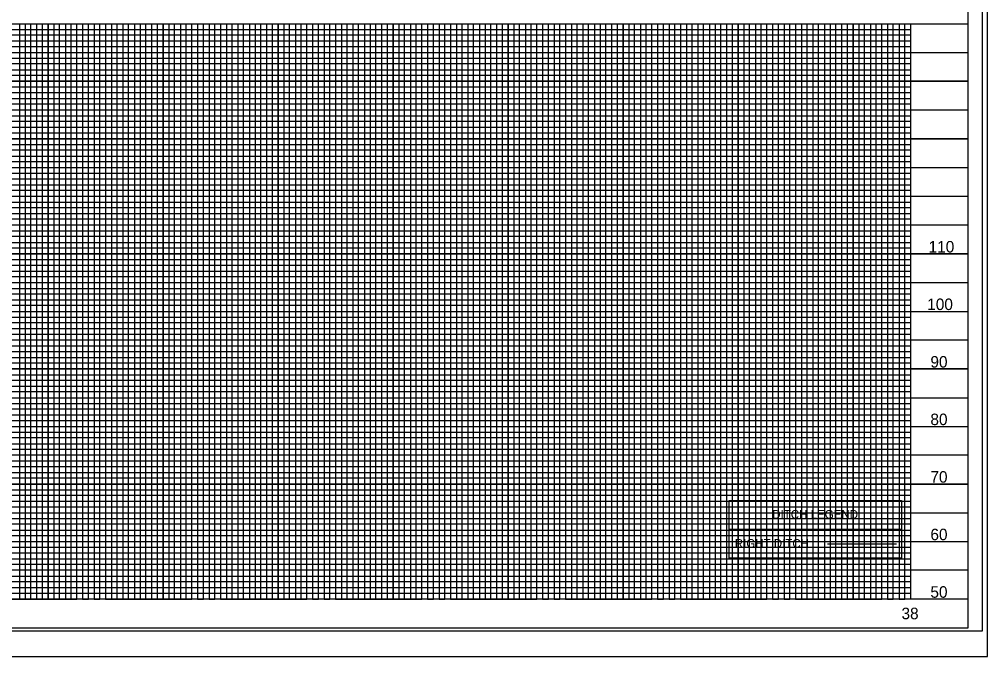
# Model space of a CAD drawing. Extents: x 2367101 to 2368930, y 803279 to 808979.
# Drawn here: x 2367943 to 2368785, y 803279 to 803833 of the extents above; entities that cross this region are included whole.
import ezdxf

# ---------------------------------------------------------------- set-up
doc = ezdxf.new("R2010")
doc.units = 0
for name, color, linetype in [('Old_Level_11', 7, 'Continuous'), ('Old_Level_12', 7, 'Continuous'), ('Old_Level_13', 7, 'Continuous'), ('Old_Level_15', 7, 'Continuous'), ('Old_Level_17', 7, 'Continuous'), ('Old_Level_19', 7, 'Continuous'), ('Old_Level_4', 7, 'Continuous'), ('Old_Level_5', 7, 'Continuous'), ('Old_Level_6', 7, 'Continuous'), ('Old_Level_60', 7, 'Continuous'), ('Old_Level_8', 7, 'Continuous'), ('Old_Level_9', 7, 'Continuous'), ('Text', 7, 'Continuous')]:
    doc.layers.add(name, color=color, linetype=linetype)

msp = doc.modelspace()

# ---------------------------------------------------------------- linework, layer by layer
at = {"layer": 'Old_Level_11'}
for p, q in [((2367967.97, 803828.98), (2368017.97, 803828.98)), ((2368067.97, 803828.98), (2368117.97, 803828.98)), ((2368167.97, 803828.98), (2368217.97, 803828.98)), ((2368267.97, 803828.98), (2368317.97, 803828.98)), ((2368367.97, 803828.98), (2368417.97, 803828.98)), ((2368467.97, 803828.98), (2368517.97, 803828.98)), ((2368567.97, 803828.98), (2368617.97, 803828.98)), ((2368667.97, 803828.98), (2368717.97, 803828.98)), ((2368667.97, 803328.98), (2368667.97, 803328.98))]:
    msp.add_line(p, q, dxfattribs=at)
for points in [[(2367917.97, 803328.98), (2367967.97, 803328.98), (2367967.97, 803828.98), (2368017.97, 803828.98), (2368017.97, 803328.98), (2368067.97, 803328.98), (2368067.97, 803828.98), (2368117.97, 803828.98), (2368117.97, 803328.98), (2368167.97, 803328.98), (2368167.97, 803828.98), (2368217.97, 803828.98), (2368217.97, 803328.98), (2368267.97, 803328.98), (2368267.97, 803828.98), (2368317.97, 803828.98), (2368317.97, 803328.98), (2368367.97, 803328.98), (2368367.97, 803828.98), (2368417.97, 803828.98), (2368417.97, 803328.98), (2368467.97, 803328.98), (2368467.97, 803828.98), (2368517.97, 803828.98), (2368517.97, 803328.98), (2368567.97, 803328.98), (2368567.97, 803828.98), (2368617.97, 803828.98), (2368617.97, 803328.98), (2368667.97, 803328.98), (2368667.97, 803328.98), (2368667.97, 803828.98), (2368717.97, 803828.98), (2368717.97, 803328.98)], [(2368767.97, 803778.98), (2367267.97, 803778.98)], [(2368767.97, 803728.98), (2367267.97, 803728.98), (2367267.97, 803678.98), (2368767.97, 803678.98)], [(2368767.97, 803628.98), (2367267.97, 803628.98), (2367267.97, 803578.98), (2368767.97, 803578.98)], [(2368767.97, 803528.98), (2367267.97, 803528.98), (2367267.97, 803478.98), (2368767.97, 803478.98)], [(2368767.97, 803428.98), (2367267.97, 803428.98), (2367267.97, 803428.98), (2367267.97, 803378.98), (2368767.97, 803378.98)], [(2368767.97, 803328.98), (2367267.97, 803328.98)]]:
    msp.add_lwpolyline(points, dxfattribs=at)
at = {"layer": 'Old_Level_12'}
for points in [[(2367892.97, 803828.98), (2367942.97, 803828.98), (2367942.97, 803328.98), (2367992.97, 803328.98), (2367992.97, 803828.98), (2368042.97, 803828.98), (2368042.97, 803328.98), (2368092.97, 803328.98), (2368092.97, 803828.98), (2368142.97, 803828.98), (2368142.97, 803328.98), (2368192.97, 803328.98), (2368192.97, 803828.98), (2368242.97, 803828.98), (2368242.97, 803328.98), (2368292.97, 803328.98), (2368292.97, 803828.98), (2368342.97, 803828.98), (2368342.97, 803328.98), (2368392.97, 803328.98), (2368392.97, 803828.98), (2368442.97, 803828.98), (2368442.97, 803328.98), (2368492.97, 803328.98), (2368492.97, 803828.98), (2368542.97, 803828.98), (2368542.97, 803328.98), (2368592.97, 803328.98), (2368592.97, 803828.98), (2368642.97, 803828.98), (2368642.97, 803328.98), (2368692.97, 803328.98), (2368692.97, 803828.98)], [(2367267.97, 803803.98), (2368767.97, 803803.98)], [(2368767.97, 803753.98), (2367267.97, 803753.98), (2367267.97, 803703.98), (2368767.97, 803703.98)], [(2368767.97, 803653.98), (2367267.97, 803653.98), (2367267.97, 803603.98), (2368767.97, 803603.98)], [(2368767.97, 803553.98), (2367267.97, 803553.98), (2367267.97, 803503.98), (2368767.97, 803503.98)], [(2368767.97, 803453.98), (2367267.97, 803453.98), (2367267.97, 803403.98), (2368767.97, 803403.98)], [(2368767.97, 803353.98), (2367267.97, 803353.98)]]:
    msp.add_lwpolyline(points, dxfattribs=at)
at = {"layer": 'Old_Level_13'}
for p, q in [((2367267.97, 803828.98), (2368767.86, 803828.98)), ((2367967.97, 803828.98), (2367967.97, 803328.98)), ((2368017.97, 803828.98), (2368017.97, 803328.98)), ((2368067.97, 803828.98), (2368067.97, 803328.98)), ((2368117.97, 803828.98), (2368117.97, 803328.98)), ((2368167.97, 803828.98), (2368167.97, 803328.98)), ((2368217.97, 803828.98), (2368217.97, 803328.98)), ((2368267.97, 803828.98), (2368267.97, 803328.98)), ((2368317.97, 803828.98), (2368317.97, 803328.98)), ((2368367.97, 803828.98), (2368367.97, 803328.98)), ((2368417.97, 803828.98), (2368417.97, 803328.98)), ((2368467.97, 803828.98), (2368467.97, 803328.98)), ((2368517.97, 803828.98), (2368517.97, 803328.98)), ((2368567.97, 803828.98), (2368567.97, 803328.98)), ((2368617.97, 803828.98), (2368617.97, 803328.98)), ((2368667.97, 803828.98), (2368667.97, 803328.98)), ((2368717.97, 803828.98), (2368717.97, 803328.98)), ((2367267.97, 803778.98), (2368767.86, 803778.98)), ((2367267.97, 803728.98), (2368767.86, 803728.98)), ((2367267.97, 803678.98), (2368767.86, 803678.98)), ((2367267.97, 803628.98), (2368767.86, 803628.98)), ((2367267.97, 803578.98), (2368767.86, 803578.98)), ((2367267.97, 803528.98), (2368767.86, 803528.98)), ((2367267.97, 803478.98), (2368767.86, 803478.98)), ((2367267.97, 803428.98), (2368767.86, 803428.98)), ((2367267.97, 803378.98), (2368767.86, 803378.98))]:
    msp.add_line(p, q, dxfattribs=at)
at = {"layer": 'Old_Level_15'}
msp.add_line((2367100.97, 803278.98), (2368784.97, 803278.98), dxfattribs=at)
at = {"layer": 'Old_Level_4'}
msp.add_lwpolyline([(2367113.97, 803301.43), (2368780.47, 803301.43), (2368780.47, 804356.53), (2367113.97, 804356.53)], close=True, dxfattribs=at)
at = {"layer": 'Old_Level_5'}
msp.add_lwpolyline([(2367317.97, 803828.98), (2368717.97, 803828.98), (2368717.97, 803328.98), (2367317.97, 803328.98)], close=True, dxfattribs=at)
at = {"layer": 'Old_Level_6'}
msp.add_lwpolyline([(2367100.97, 803278.98), (2368784.97, 803278.98), (2368784.97, 804378.98), (2367100.97, 804378.98)], close=True, dxfattribs=at)
at = {"layer": 'Old_Level_60'}
for points in [[(2368560.13, 803414.54), (2368710.13, 803414.54), (2368710.13, 803389.54), (2368560.13, 803389.54)], [(2368560.13, 803389.54), (2368710.13, 803389.54), (2368710.13, 803364.54), (2368560.13, 803364.54)]]:
    msp.add_lwpolyline(points, close=True, dxfattribs=at)
at = {"layer": 'Old_Level_8'}
for p, q in [((2367317.97, 803823.98), (2368717.97, 803823.98)), ((2368717.97, 803818.98), (2367317.97, 803818.98)), ((2367317.97, 803813.98), (2368717.97, 803813.98)), ((2368717.97, 803808.98), (2367317.97, 803808.98)), ((2367317.97, 803798.98), (2368717.97, 803798.98)), ((2368717.97, 803793.98), (2367317.97, 803793.98)), ((2367317.97, 803788.98), (2368717.97, 803788.98)), ((2368717.97, 803783.98), (2367317.97, 803783.98)), ((2367317.97, 803773.98), (2368717.97, 803773.98)), ((2368717.97, 803768.98), (2367317.97, 803768.98)), ((2367317.97, 803763.98), (2368717.97, 803763.98)), ((2368717.97, 803758.98), (2367317.97, 803758.98)), ((2367317.97, 803748.98), (2368717.97, 803748.98)), ((2368717.97, 803743.98), (2367317.97, 803743.98)), ((2367317.97, 803738.98), (2368717.97, 803738.98)), ((2368717.97, 803733.98), (2367317.97, 803733.98)), ((2367317.97, 803723.98), (2368717.97, 803723.98)), ((2368717.97, 803718.98), (2367317.97, 803718.98)), ((2367317.97, 803713.98), (2368717.97, 803713.98)), ((2368717.97, 803708.98), (2367317.97, 803708.98)), ((2367317.97, 803698.98), (2368717.97, 803698.98)), ((2368717.97, 803693.98), (2367317.97, 803693.98)), ((2367317.97, 803688.98), (2368717.97, 803688.98)), ((2368717.97, 803683.98), (2367317.97, 803683.98)), ((2367317.97, 803673.98), (2368717.97, 803673.98)), ((2368717.97, 803668.98), (2367317.97, 803668.98)), ((2367317.97, 803663.98), (2368717.97, 803663.98)), ((2368717.97, 803658.98), (2367317.97, 803658.98)), ((2367317.97, 803648.98), (2368717.97, 803648.98)), ((2368717.97, 803643.98), (2367317.97, 803643.98)), ((2367317.97, 803638.98), (2368717.97, 803638.98)), ((2368717.97, 803633.98), (2367317.97, 803634.13)), ((2367317.97, 803623.98), (2368717.97, 803623.98)), ((2368717.97, 803618.98), (2367317.97, 803618.98)), ((2367317.97, 803613.98), (2368717.97, 803613.98)), ((2368717.97, 803608.98), (2367317.97, 803608.98)), ((2367317.97, 803598.98), (2368717.97, 803598.98)), ((2368717.97, 803593.98), (2367317.97, 803593.98)), ((2367317.97, 803588.98), (2368717.97, 803588.98)), ((2368717.97, 803583.98), (2367317.97, 803583.98)), ((2367317.97, 803573.98), (2368717.97, 803573.98)), ((2368717.97, 803568.98), (2367317.97, 803568.98)), ((2367317.97, 803563.98), (2368717.97, 803563.98)), ((2368717.97, 803558.98), (2367317.97, 803558.98)), ((2367317.97, 803548.98), (2368717.97, 803548.98)), ((2368717.97, 803543.98), (2367317.97, 803543.98)), ((2367317.97, 803538.98), (2368717.97, 803538.98)), ((2368717.97, 803533.98), (2367317.97, 803533.98)), ((2367317.97, 803523.98), (2368717.97, 803523.98)), ((2368717.97, 803518.98), (2367317.97, 803518.98)), ((2367317.97, 803513.98), (2368717.97, 803513.98)), ((2368717.97, 803508.98), (2367317.97, 803508.98)), ((2367317.97, 803498.98), (2368717.97, 803498.98)), ((2368717.97, 803493.98), (2367317.97, 803493.98)), ((2367317.97, 803488.98), (2368717.97, 803488.98)), ((2368717.97, 803483.98), (2367317.97, 803483.98)), ((2367317.97, 803473.98), (2368717.97, 803473.98)), ((2368717.97, 803468.98), (2367317.97, 803468.98)), ((2367317.97, 803463.98), (2368717.97, 803463.98)), ((2368717.97, 803458.98), (2367317.97, 803458.98)), ((2367317.97, 803448.98), (2368717.97, 803448.98)), ((2368717.97, 803443.98), (2367317.97, 803443.98)), ((2367317.97, 803438.98), (2368717.97, 803438.98)), ((2368717.97, 803433.98), (2367317.97, 803433.98)), ((2367317.97, 803423.98), (2368717.97, 803423.98)), ((2368717.97, 803418.98), (2367317.97, 803418.98)), ((2367317.97, 803413.98), (2368717.97, 803413.98)), ((2368717.97, 803408.98), (2367317.97, 803408.98)), ((2367317.97, 803398.98), (2368717.97, 803398.98)), ((2368717.97, 803393.98), (2367317.97, 803393.98)), ((2367317.97, 803388.98), (2368717.97, 803388.98)), ((2368717.97, 803383.98), (2367317.97, 803383.98)), ((2367317.97, 803373.98), (2368717.97, 803373.98)), ((2368717.97, 803368.98), (2367317.97, 803368.98)), ((2367317.97, 803363.98), (2368717.97, 803363.98)), ((2368717.97, 803358.98), (2367317.97, 803358.98)), ((2367317.97, 803348.98), (2368717.97, 803348.98)), ((2368717.97, 803343.98), (2367317.97, 803343.98)), ((2367317.97, 803338.98), (2368717.97, 803338.98)), ((2367317.97, 803333.98), (2368717.97, 803333.98)), ((2368717.97, 803333.98), (2368717.97, 803333.98))]:
    msp.add_line(p, q, dxfattribs=at)
for points in [[(2367937.97, 803828.98), (2367947.97, 803828.98), (2367947.97, 803328.98), (2367952.97, 803328.98), (2367952.97, 803828.98), (2367957.97, 803828.98), (2367957.97, 803328.98), (2367962.97, 803328.98), (2367962.97, 803828.98), (2367972.97, 803828.98), (2367972.97, 803328.98), (2367972.97, 803328.98), (2367977.97, 803328.98), (2367977.97, 803828.98), (2367982.97, 803828.98), (2367982.97, 803328.98), (2367987.97, 803328.98), (2367987.97, 803828.98), (2367997.97, 803828.98), (2367997.97, 803328.98), (2368002.97, 803328.98), (2368002.97, 803828.98), (2368007.97, 803828.98), (2368007.97, 803328.98), (2368012.97, 803328.98), (2368012.97, 803828.98), (2368022.97, 803828.98), (2368022.97, 803328.98), (2368027.97, 803328.98), (2368027.97, 803828.98), (2368032.97, 803828.98), (2368032.97, 803328.98), (2368037.97, 803328.98), (2368037.97, 803828.98), (2368047.97, 803828.98), (2368047.97, 803328.98), (2368052.97, 803328.98), (2368052.97, 803828.98), (2368057.97, 803828.98), (2368057.97, 803328.98), (2368062.97, 803328.98), (2368062.97, 803828.98), (2368072.97, 803828.98), (2368072.97, 803328.98), (2368077.97, 803328.98), (2368077.97, 803828.98), (2368082.97, 803828.98), (2368082.97, 803328.98), (2368087.97, 803328.98), (2368087.97, 803828.98), (2368097.97, 803828.98), (2368097.97, 803328.98), (2368102.97, 803328.98), (2368102.97, 803828.98), (2368107.97, 803828.98), (2368107.97, 803328.98), (2368112.97, 803328.98), (2368112.97, 803828.98), (2368122.97, 803828.98), (2368122.97, 803328.98), (2368127.67, 803329.53), (2368127.97, 803328.98), (2368127.97, 803828.98), (2368132.97, 803828.98), (2368132.97, 803328.98), (2368137.97, 803328.98), (2368137.97, 803828.98), (2368147.97, 803828.98), (2368147.97, 803328.98), (2368152.97, 803328.98)], [(2368152.97, 803328.98), (2368152.97, 803828.98), (2368157.97, 803828.98), (2368157.97, 803328.98), (2368162.97, 803328.98), (2368162.97, 803828.98), (2368172.97, 803828.98), (2368172.97, 803328.98), (2368177.97, 803328.98), (2368177.97, 803828.98), (2368182.97, 803828.98), (2368182.97, 803328.98), (2368187.97, 803328.98), (2368187.97, 803828.98), (2368197.97, 803828.98), (2368197.97, 803328.98), (2368202.97, 803328.98), (2368202.97, 803828.98), (2368207.97, 803828.98), (2368207.97, 803328.98), (2368212.97, 803328.98), (2368212.97, 803828.98), (2368222.97, 803828.98), (2368222.97, 803328.98), (2368227.97, 803328.98), (2368227.97, 803828.98), (2368232.97, 803828.98), (2368232.97, 803328.98), (2368237.97, 803328.98), (2368237.97, 803828.98), (2368247.97, 803828.98), (2368247.97, 803328.98), (2368252.97, 803328.98), (2368252.97, 803828.98), (2368257.97, 803828.98), (2368257.97, 803328.98), (2368262.97, 803328.98), (2368262.97, 803828.98), (2368272.97, 803828.98), (2368272.97, 803328.98), (2368277.97, 803328.98), (2368277.97, 803828.98), (2368282.97, 803828.98), (2368282.97, 803328.98), (2368287.97, 803328.98), (2368287.97, 803828.98), (2368297.97, 803828.98), (2368297.97, 803328.98), (2368302.97, 803328.98), (2368302.97, 803828.98), (2368307.97, 803828.98), (2368307.97, 803328.98), (2368312.97, 803328.98), (2368312.97, 803828.98), (2368322.97, 803828.98), (2368322.97, 803328.98), (2368327.97, 803328.98), (2368327.97, 803828.98), (2368332.97, 803828.98), (2368332.97, 803328.98), (2368337.97, 803328.98), (2368337.97, 803828.98), (2368347.97, 803828.98), (2368347.97, 803328.98), (2368352.97, 803328.98), (2368352.97, 803828.98), (2368357.97, 803828.98), (2368357.97, 803328.98), (2368362.97, 803328.98), (2368362.97, 803828.98), (2368372.97, 803828.98), (2368372.97, 803328.98), (2368377.97, 803328.98), (2368377.97, 803828.98), (2368382.97, 803828.98), (2368382.97, 803328.98), (2368387.97, 803328.98), (2368387.97, 803828.98), (2368397.97, 803828.98), (2368397.97, 803328.98), (2368402.97, 803328.98), (2368402.97, 803828.98), (2368407.97, 803828.98), (2368407.97, 803328.98), (2368412.97, 803328.98), (2368412.97, 803828.98), (2368422.97, 803828.98), (2368422.97, 803328.98), (2368427.97, 803328.98), (2368427.97, 803828.98), (2368432.97, 803828.98), (2368432.97, 803328.98), (2368437.97, 803328.98), (2368437.97, 803828.98), (2368447.97, 803828.98), (2368447.97, 803328.98), (2368452.97, 803328.98), (2368452.97, 803828.98), (2368457.97, 803828.98), (2368457.97, 803328.98)], [(2368457.97, 803328.98), (2368462.97, 803328.98), (2368462.97, 803828.98), (2368472.97, 803828.98), (2368472.97, 803328.98), (2368477.97, 803328.98), (2368477.97, 803828.98), (2368482.97, 803828.98), (2368482.97, 803328.98), (2368487.97, 803328.98), (2368487.97, 803828.98), (2368497.97, 803828.98), (2368497.97, 803328.98), (2368502.97, 803328.98), (2368502.97, 803828.98), (2368507.97, 803828.98), (2368507.97, 803328.98), (2368512.97, 803328.98), (2368512.97, 803828.98), (2368522.97, 803828.98), (2368522.97, 803328.98), (2368527.97, 803328.98), (2368527.97, 803828.98), (2368532.97, 803828.98), (2368532.97, 803328.98), (2368537.97, 803328.98), (2368537.97, 803828.98), (2368547.97, 803828.98), (2368547.97, 803328.98), (2368552.97, 803328.98), (2368552.97, 803828.98), (2368557.97, 803828.98), (2368557.97, 803328.98), (2368562.97, 803328.98), (2368562.97, 803828.98), (2368572.97, 803828.98), (2368572.97, 803328.98), (2368577.97, 803328.98), (2368577.97, 803828.98), (2368582.97, 803828.98), (2368582.97, 803328.98), (2368587.97, 803328.98), (2368587.97, 803828.98), (2368597.97, 803828.98), (2368597.97, 803328.98), (2368602.97, 803328.98), (2368602.97, 803828.98), (2368607.97, 803828.98), (2368607.97, 803328.98), (2368612.97, 803328.98), (2368612.97, 803828.98), (2368622.97, 803828.98), (2368622.97, 803328.98), (2368627.97, 803328.98), (2368627.97, 803828.98), (2368632.97, 803828.98), (2368632.97, 803328.98), (2368637.97, 803328.98), (2368637.97, 803828.98), (2368647.97, 803828.98), (2368647.97, 803328.98), (2368652.97, 803328.98), (2368652.97, 803828.98), (2368657.97, 803828.98), (2368657.97, 803328.98), (2368662.97, 803328.98), (2368662.97, 803828.98), (2368672.97, 803828.98), (2368672.97, 803328.98), (2368677.97, 803328.98), (2368677.97, 803828.98), (2368682.97, 803828.98), (2368682.97, 803328.98), (2368687.97, 803328.98), (2368687.97, 803828.98), (2368697.97, 803828.98), (2368697.97, 803328.98), (2368702.97, 803328.98), (2368702.97, 803828.98), (2368707.97, 803828.98), (2368707.97, 803328.98), (2368712.97, 803328.98), (2368712.97, 803828.98), (2368717.97, 803828.98)]]:
    msp.add_lwpolyline(points, dxfattribs=at)
at = {"layer": 'Old_Level_9'}
for p, q in [((2367267.97, 803828.98), (2368767.97, 803828.98)), ((2368767.97, 803328.98), (2367267.97, 803328.98)), ((2367267.97, 803303.98), (2368767.97, 803303.98))]:
    msp.add_line(p, q, dxfattribs=at)
msp.add_lwpolyline([(2368767.97, 804353.98), (2367267.97, 804353.98), (2367267.97, 803303.98), (2368767.97, 803303.98)], close=True, dxfattribs=at)
at = {"layer": 'Text'}
for p, q in [((2368560.13, 803374.54), (2368560.13, 803374.54)), ((2368645.68, 803376.89), (2368705.68, 803376.89))]:
    msp.add_line(p, q, dxfattribs=at)

# ---------------------------------------------------------------- texts
at = {"layer": 'Old_Level_17'}
for s, p in [('110', (2368733.65, 803630.15)), ('100', (2368732.46, 803580.15)), ('90', (2368735.21, 803530.15)), ('80', (2368735.21, 803480.15)), ('70', (2368735.21, 803430.15)), ('60', (2368735.21, 803380.15)), ('50', (2368735.21, 803330.15))]:
    msp.add_text(s, height=10, dxfattribs=at).set_placement(p)
at = {"layer": 'Old_Level_19'}
msp.add_text('38', height=10, dxfattribs=at).set_placement((2368710.08, 803311.48))
at = {"layer": 'Text'}
for s, height, p in [('DITCH LEGEND', 7.5, (2368597.63, 803398.89)), ('RIGHT DITCH', 7.485, (2368565.13, 803373.64))]:
    msp.add_text(s, height=height, dxfattribs=at).set_placement(p)

doc.saveas('drawing.dxf')
